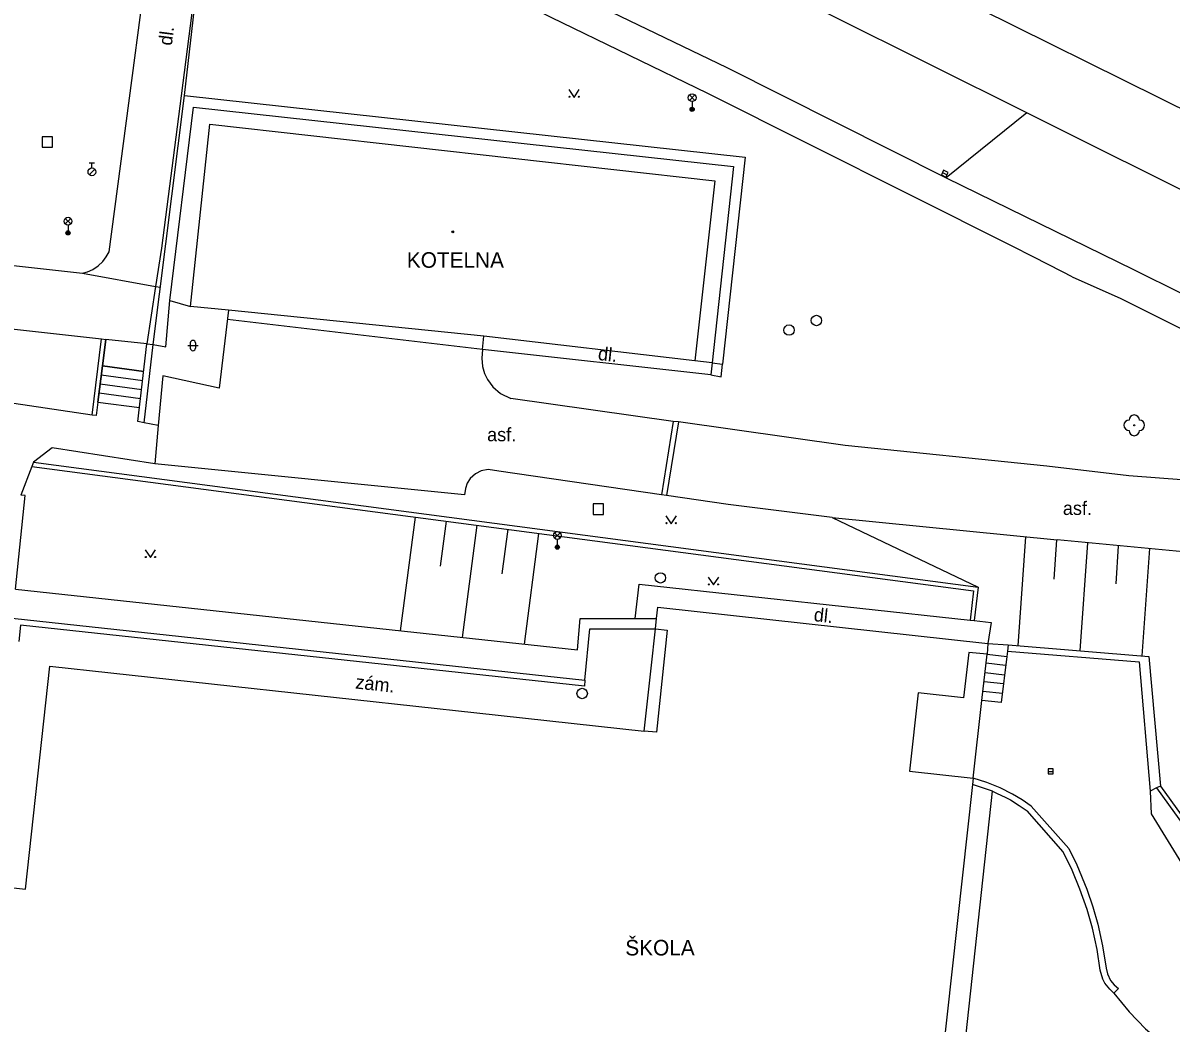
# Model space of a CAD drawing. Extents: x -602419 to -601554, y -1162937 to -1162362.
# Drawn here: x -602308.5 to -602253.1, y -1162567.6 to -1162519.4 of the extents above; entities that cross this region are included whole.
import ezdxf

# ---------------------------------------------------------------- set-up
doc = ezdxf.new("R2010")
doc.units = 0
doc.layers.add('Podklad', color=7, linetype='Continuous')

msp = doc.modelspace()

# ---------------------------------------------------------------- linework, layer by layer
at = {"layer": 'Podklad'}
for p, q in [((-602276.3625, -1162523.18), (-602276.0975, -1162522.915)), ((-602276.3625, -1162522.915), (-602276.0975, -1162523.18)), ((-602276.23, -1162523.235), (-602276.23, -1162523.61)), ((-602305.2889, -1162526.756), (-602305.0239, -1162526.491)), ((-602305.2849, -1162526.1825), (-602305.0349, -1162526.1825)), ((-602305.1599, -1162526.4325), (-602305.1599, -1162526.1825)), ((-602264.1618, -1162526.6541), (-602263.9382, -1162526.7659)), ((-602306.4425, -1162529.13), (-602306.1775, -1162528.865)), ((-602306.4425, -1162528.865), (-602306.1775, -1162529.13)), ((-602306.31, -1162529.185), (-602306.31, -1162529.56)), ((-602300.418, -1162534.863), (-602300.418, -1162535.113)), ((-602300.168, -1162534.863), (-602300.168, -1162535.113)), ((-602300.543, -1162534.988), (-602300.043, -1162534.988)), ((-602282.8625, -1162544.27), (-602282.5975, -1162544.005)), ((-602282.8625, -1162544.005), (-602282.5975, -1162544.27)), ((-602282.73, -1162544.325), (-602282.73, -1162544.7)), ((-602259.075, -1162555.5), (-602258.825, -1162555.5))]:
    msp.add_line(p, q, dxfattribs=at)
for points in [[(-602239.67, -1162530.01), (-602276.39, -1162511.82), (-602283.55, -1162508.2199)], [(-602304.33, -1162530.4699), (-602301.71, -1162510.68)], [(-602299.39, -1162511.57), (-602300.85, -1162522.96)], [(-602300.69, -1162522.94), (-602299.39, -1162511.57)], [(-602257.9099, -1162531.68), (-602258.37, -1162531.44), (-602259.79, -1162530.71), (-602260.81, -1162530.2), (-602275.4699, -1162522.85), (-602283.02, -1162519.18), (-602286.67, -1162517.34), (-602289, -1162516.17), (-602292.19, -1162514.68), (-602295.08, -1162513.4), (-602298.14, -1162512.15), (-602299.39, -1162511.57)], [(-602260.1, -1162523.77), (-602278.919, -1162514.3799)], [(-602285.95, -1162516), (-602282.27, -1162517.87), (-602274.56, -1162521.6)], [(-602274.56, -1162521.6), (-602263.98, -1162526.9)], [(-602282.17, -1162522.655), (-602281.92, -1162523.03), (-602281.67, -1162522.655)], [(-602302.21, -1162534.94), (-602300.69, -1162522.94), (-602273.68, -1162525.92), (-602274.76, -1162535.88)], [(-602300.85, -1162522.96), (-602301.81, -1162530.29), (-602302.09, -1162532.14)], [(-602300.85, -1162522.96), (-602301.81, -1162530.29), (-602302.09, -1162532.14)], [(-602301.4, -1162532.82), (-602300.26, -1162523.5), (-602274.24, -1162526.36), (-602275.26, -1162535.82)], [(-602241.24, -1162533.19), (-602260.1, -1162523.77), (-602263.98, -1162526.9)], [(-602300.4099, -1162533.11), (-602299.4699, -1162524.33)], [(-602299.4699, -1162524.33), (-602275.14, -1162527.05)], [(-602275.14, -1162527.05), (-602276.1, -1162535.7199)], [(-602263.98, -1162526.9), (-602254.96, -1162531.32), (-602243.31, -1162537.1), (-602241.24, -1162533.19)], [(-602319.37, -1162529.98), (-602305.62, -1162531.5)], [(-602305.62, -1162531.5), (-602305.37, -1162531.43), (-602305.12, -1162531.32), (-602304.85, -1162531.14), (-602304.64, -1162530.94), (-602304.4699, -1162530.7199), (-602304.33, -1162530.4699)], [(-602305.62, -1162531.5), (-602302.09, -1162532.14)], [(-602330.32, -1162531.82), (-602304.69, -1162534.67)], [(-602257.9099, -1162531.68), (-602255.57, -1162532.7199), (-602244.17, -1162538.42)], [(-602302.09, -1162532.14), (-602302.51, -1162534.9)], [(-602302.09, -1162532.14), (-602302.51, -1162534.9)], [(-602302.09, -1162532.14), (-602301.8604, -1162532.1797)], [(-602302.21, -1162534.94), (-602301.6, -1162535.05), (-602301.4, -1162532.82)], [(-602301.4, -1162532.82), (-602300.4099, -1162533.11)], [(-602298.58, -1162533.29), (-602300.4099, -1162533.11)], [(-602298.58, -1162533.29), (-602299.02, -1162537.04), (-602301.74, -1162536.44)], [(-602286.34, -1162535.18), (-602298.632, -1162533.734)], [(-602286.27, -1162534.53), (-602298.58, -1162533.29)], [(-602305.15, -1162538.34), (-602328.78, -1162534.82)], [(-602305.15, -1162538.34), (-602304.69, -1162534.67)], [(-602304.69, -1162534.67), (-602304.49, -1162534.7)], [(-602304.65, -1162535.9699), (-602304.49, -1162534.7)], [(-602304.49, -1162534.7), (-602304.65, -1162535.9699)], [(-602302.51, -1162534.9), (-602304.49, -1162534.7)], [(-602302.94, -1162538.65), (-602302.51, -1162534.9)], [(-602302.51, -1162534.9), (-602302.21, -1162534.94)], [(-602286.34, -1162535.18), (-602286.27, -1162534.53)], [(-602276.1, -1162535.7199), (-602286.27, -1162534.53)], [(-602302.64, -1162538.71), (-602302.21, -1162534.94)], [(-602286.34, -1162535.18), (-602286.37, -1162535.59), (-602286.33, -1162536), (-602286.23, -1162536.33), (-602286.09, -1162536.62), (-602285.84, -1162536.9699), (-602285.4699, -1162537.3), (-602284.9699, -1162537.54)], [(-602275.32, -1162536.4), (-602286.34, -1162535.18)], [(-602304.87, -1162537.71), (-602304.65, -1162535.9699)], [(-602304.65, -1162535.9699), (-602304.87, -1162537.71)], [(-602302.6636, -1162536.2395), (-602304.65, -1162535.9699)], [(-602304.65, -1162535.9699), (-602302.6599, -1162536.24)], [(-602275.26, -1162535.82), (-602276.1, -1162535.7199)], [(-602275.26, -1162535.82), (-602275.32, -1162536.4)], [(-602275.32, -1162536.4), (-602274.83, -1162536.4999), (-602274.7629, -1162535.8797)], [(-602275.26, -1162535.82), (-602274.76, -1162535.88)], [(-602302.71, -1162536.68), (-602304.71, -1162536.4099)], [(-602301.74, -1162536.44), (-602301.9699, -1162538.84)], [(-602304.76, -1162536.84), (-602302.76, -1162537.11)], [(-602302.81, -1162537.55), (-602304.81, -1162537.28)], [(-602277.14, -1162538.64), (-602284.9699, -1162537.54)], [(-602304.87, -1162537.71), (-602304.95, -1162538.36)], [(-602304.87, -1162537.71), (-602302.8631, -1162537.9796)], [(-602304.87, -1162537.71), (-602302.86, -1162537.98)], [(-602304.95, -1162538.36), (-602305.15, -1162538.34)], [(-602302.64, -1162538.71), (-602302.94, -1162538.65)], [(-602301.9699, -1162538.84), (-602302.64, -1162538.71)], [(-602277.14, -1162538.64), (-602277.7, -1162542.18)], [(-602276.89, -1162538.67), (-602277.46, -1162542.21)], [(-602276.89, -1162538.67), (-602277.14, -1162538.64)], [(-602268.86, -1162539.8), (-602276.89, -1162538.67)], [(-602301.9699, -1162538.84), (-602302.13, -1162540.69)], [(-602259.13, -1162540.8), (-602268.86, -1162539.8)], [(-602302.13, -1162540.69), (-602307.08, -1162539.9099), (-602307.9699, -1162540.61)], [(-602308.05, -1162540.81), (-602308.58, -1162542.19)], [(-602307.9699, -1162540.61), (-602308.05, -1162540.81)], [(-602308.05, -1162540.81), (-602262.67, -1162546.81), (-602262.83, -1162548.2199)], [(-602307.9699, -1162540.61), (-602262.45, -1162546.63)], [(-602287.2, -1162542.18), (-602302.13, -1162540.69)], [(-602285.54, -1162541.04), (-602286.06, -1162540.96), (-602286.4, -1162541.03), (-602286.67, -1162541.17), (-602286.92, -1162541.39), (-602287.07, -1162541.61), (-602287.1599, -1162541.87), (-602287.2, -1162542.18)], [(-602255.18, -1162541.26), (-602259.13, -1162540.8)], [(-602277.7, -1162542.18), (-602285.54, -1162541.04)], [(-602251.17, -1162541.57), (-602255.18, -1162541.26)], [(-602308.85, -1162546.73), (-602308.38, -1162542.21), (-602308.58, -1162542.19)], [(-602277.46, -1162542.21), (-602277.7, -1162542.18)], [(-602269.48, -1162543.27), (-602274.49, -1162542.64), (-602277.46, -1162542.21)], [(-602277.49, -1162543.195), (-602277.24, -1162543.57), (-602276.99, -1162543.195)], [(-602289.58, -1162543.25), (-602290.3, -1162548.73)], [(-602288.09, -1162543.45), (-602288.38, -1162545.62)], [(-602286.6, -1162543.64), (-602287.32, -1162549.05)], [(-602269.48, -1162543.27), (-602258.63, -1162544.35)], [(-602269.48, -1162543.27), (-602262.45, -1162546.63)], [(-602285.11, -1162543.84), (-602285.4, -1162545.99)], [(-602283.63, -1162544.04), (-602284.33, -1162549.37)], [(-602260.1599, -1162544.2), (-602260.53, -1162549.45)], [(-602302.59, -1162544.825), (-602302.34, -1162545.2), (-602302.09, -1162544.825)], [(-602258.67, -1162544.35), (-602258.8, -1162546.24)], [(-602252.57, -1162544.92), (-602258.63, -1162544.35)], [(-602257.18, -1162544.49), (-602257.54, -1162549.69)], [(-602255.69, -1162544.63), (-602255.81, -1162546.4699)], [(-602254.19, -1162544.77), (-602254.55, -1162549.94)], [(-602278.98, -1162548.14), (-602278.79, -1162546.48), (-602262.83, -1162548.2199)], [(-602275.45, -1162546.145), (-602275.2, -1162546.52), (-602274.95, -1162546.145)], [(-602308.85, -1162546.73), (-602281.76, -1162549.65), (-602281.62, -1162548.14), (-602278.98, -1162548.14)], [(-602262.45, -1162546.63), (-602262.63, -1162548.24)], [(-602277.94, -1162548.14), (-602277.88, -1162547.59)], [(-602277.88, -1162547.59), (-602261.9699, -1162549.34)], [(-602309, -1162548.12), (-602281.4, -1162551.1)], [(-602278.98, -1162548.14), (-602277.94, -1162548.14)], [(-602277.99, -1162548.64), (-602277.94, -1162548.14)], [(-602281.4, -1162551.1), (-602281.42, -1162551.4), (-602308.6, -1162548.46), (-602308.68, -1162549.25)], [(-602281.4, -1162551.1), (-602281.1599, -1162548.64), (-602277.99, -1162548.64)], [(-602278.2, -1162550.53), (-602277.99, -1162548.64)], [(-602277.99, -1162548.64), (-602277.43, -1162548.7)], [(-602277.43, -1162548.7), (-602277.94, -1162553.62)], [(-602262.83, -1162548.2199), (-602262.63, -1162548.24)], [(-602262.63, -1162548.24), (-602261.82, -1162548.33), (-602261.9699, -1162549.34)], [(-602262.9, -1162549.77), (-602263.15, -1162551.96)], [(-602262.01, -1162549.85), (-602262.9, -1162549.77)], [(-602261.9699, -1162549.34), (-602262.01, -1162549.85)], [(-602261.9699, -1162549.34), (-602261, -1162549.4099)], [(-602261.03, -1162549.71), (-602261.06, -1162549.96), (-602261.33, -1162552.18)], [(-602261, -1162549.4099), (-602261.03, -1162549.71)], [(-602261.03, -1162549.71), (-602254.69, -1162550.23)], [(-602261, -1162549.4099), (-602254.21, -1162549.9699), (-602253.65, -1162556.2199)], [(-602262.26, -1162552.08), (-602262.01, -1162549.85)], [(-602261.12, -1162550.4), (-602262.06, -1162550.29)], [(-602262.01, -1162549.85), (-602261.06, -1162549.96)], [(-602254.69, -1162550.23), (-602254.15, -1162556.45)], [(-602308.36, -1162561.17), (-602307.18, -1162550.43)], [(-602307.18, -1162550.43), (-602286.61, -1162552.68)], [(-602278.54, -1162553.57), (-602278.2, -1162550.53)], [(-602262.11, -1162550.74), (-602261.17, -1162550.85)], [(-602261.2199, -1162551.29), (-602262.1599, -1162551.19)], [(-602265.33, -1162551.7199), (-602265.75, -1162555.49)], [(-602263.15, -1162551.96), (-602265.33, -1162551.7199)], [(-602262.21, -1162551.63), (-602261.27, -1162551.74)], [(-602262.69, -1162555.83), (-602262.26, -1162552.08)], [(-602261.33, -1162552.18), (-602262.26, -1162552.08)], [(-602286.61, -1162552.68), (-602278.54, -1162553.57)], [(-602277.94, -1162553.62), (-602278.54, -1162553.57)], [(-602265.75, -1162555.49), (-602262.69, -1162555.83)], [(-602262.69, -1162555.83), (-602262.7199, -1162556.14)], [(-602259.89, -1162557.17), (-602260.32, -1162556.87), (-602260.78, -1162556.6), (-602261.39, -1162556.3), (-602262.02, -1162556.04), (-602262.69, -1162555.83)], [(-602262.7199, -1162556.14), (-602265.43, -1162580.74)], [(-602264.4699, -1162581.45), (-602261.75, -1162556.46)], [(-602261.75, -1162556.46), (-602262.7199, -1162556.14)], [(-602261.75, -1162556.46), (-602261.52, -1162556.56), (-602261.14, -1162556.74), (-602260.89, -1162556.88), (-602260.4699, -1162557.14), (-602260.08, -1162557.4)], [(-602253.84, -1162556.3), (-602254.15, -1162556.45)], [(-602254.15, -1162556.45), (-602254.1, -1162557.54), (-602248.68, -1162566.38), (-602248.55, -1162566.32)], [(-602253.65, -1162556.2199), (-602253.84, -1162556.3)], [(-602253.84, -1162556.3), (-602248.3, -1162563.98), (-602248.55, -1162566.32)], [(-602253.65, -1162556.2199), (-602248.09, -1162563.93)], [(-602258.35, -1162559.38), (-602260.08, -1162557.4)], [(-602259.89, -1162557.17), (-602258.08, -1162559.2199)], [(-602258.08, -1162559.2199), (-602257.68, -1162560.01), (-602257.2, -1162561.18), (-602256.92, -1162562.02), (-602256.68, -1162562.87), (-602256.45, -1162563.9), (-602256.28, -1162564.99), (-602256.21, -1162565.26), (-602256.06, -1162565.58), (-602255.89, -1162565.78), (-602255.68, -1162565.96)], [(-602255.9, -1162566.18), (-602256.1, -1162565.99), (-602256.33, -1162565.7), (-602256.43, -1162565.52), (-602256.56, -1162565.08), (-602256.7, -1162564.08), (-602256.93, -1162563.06), (-602257.19, -1162562.15), (-602257.54, -1162561.17), (-602257.92, -1162560.26), (-602258.35, -1162559.38)], [(-602312.93, -1162560.67), (-602308.36, -1162561.17)], [(-602255.68, -1162565.96), (-602255.9, -1162566.18)], [(-602255.9, -1162566.18), (-602255.17, -1162567.08), (-602254.37, -1162567.9), (-602253.62, -1162568.55), (-602252.8, -1162569.12)]]:
    msp.add_lwpolyline(points, dxfattribs=at)
for points in [[(-602307.56, -1162525.43), (-602307.06, -1162525.43), (-602307.06, -1162524.93), (-602307.56, -1162524.93)], [(-602264.2177, -1162526.766), (-602263.994, -1162526.8777), (-602263.8823, -1162526.654), (-602264.106, -1162526.5423)], [(-602281, -1162543.12), (-602280.5, -1162543.12), (-602280.5, -1162542.62), (-602281, -1162542.62)], [(-602259.075, -1162555.625), (-602258.825, -1162555.625), (-602258.825, -1162555.375), (-602259.075, -1162555.375)]]:
    msp.add_lwpolyline(points, close=True, dxfattribs=at)
for centre, radius in [((-602282.1451, -1162523.0049), 0.025), ((-602281.6954, -1162523.0049), 0.025), ((-602276.23, -1162523.0475), 0.1875), ((-602276.23, -1162523.61), 0.1), ((-602276.23, -1162523.61), 0.0723), ((-602276.23, -1162523.61), 0.0438), ((-602305.1599, -1162526.62), 0.1875), ((-602306.31, -1162528.9975), 0.1875), ((-602306.31, -1162529.56), 0.1), ((-602306.31, -1162529.56), 0.0723), ((-602306.31, -1162529.56), 0.0438), ((-602287.77, -1162529.51), 0.045), ((-602287.77, -1162529.51), 0.0199), ((-602270.24, -1162533.78), 0.25), ((-602271.56, -1162534.24), 0.25), ((-602254.92, -1162538.83), 0.025), ((-602277.4651, -1162543.5449), 0.025), ((-602277.0154, -1162543.5449), 0.025), ((-602282.73, -1162544.1375), 0.1875), ((-602282.73, -1162544.7), 0.1), ((-602282.73, -1162544.7), 0.0723), ((-602282.73, -1162544.7), 0.0438), ((-602302.5651, -1162545.1749), 0.025), ((-602302.1154, -1162545.1749), 0.025), ((-602277.76, -1162546.18), 0.25), ((-602275.4251, -1162546.4949), 0.025), ((-602274.9754, -1162546.4949), 0.025), ((-602281.53, -1162551.75), 0.25)]:
    msp.add_circle(centre, radius, dxfattribs=at)
for centre, radius, start, end in [((-602300.2928, -1162534.8631), 0.125, 0, 180), ((-602300.2928, -1162535.1131), 0.125, 180, 0), ((-602255.17, -1162538.83), 0.25, 90, 270), ((-602254.92, -1162538.58), 0.25, 0, 180), ((-602254.67, -1162538.83), 0.25, 270, 90), ((-602254.92, -1162539.08), 0.25, 180, 0)]:
    msp.add_arc(centre, radius, start, end, dxfattribs=at)

# ---------------------------------------------------------------- texts
for s, rotation, p in [('dl.', 82.77, (-602301.31, -1162520.56)), ('dl.', 353.67, (-602280.79, -1162535.68)), ('dl.', 353.72, (-602270.39, -1162548.26)), (' zám.', 353.76, (-602292.7199, -1162551.48))]:
    msp.add_text(s, height=0.65, rotation=rotation, dxfattribs=at).set_placement(p)
for s, height, p in [('KOTELNA', 0.75, (-602289.98, -1162531.24)), ('asf.', 0.65, (-602286.11, -1162539.6)), ('asf.', 0.65, (-602258.36, -1162543.15)), ('ŠKOLA', 0.75, (-602279.45, -1162564.37))]:
    msp.add_text(s, height=height, dxfattribs=at).set_placement(p)

doc.saveas('drawing.dxf')
